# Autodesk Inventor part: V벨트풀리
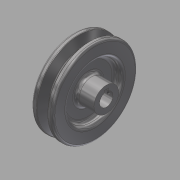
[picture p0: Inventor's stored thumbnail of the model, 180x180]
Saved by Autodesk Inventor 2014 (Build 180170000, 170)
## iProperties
Created: 2015-11
Part Number: V벨트풀리
Material: 강철, 탄소
Document SubType Name: Modeling
Designer: mduedu
Density: 1 g/cm^3
Appearance: 반광택
Author: mduedu
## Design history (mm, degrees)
sketch "스케치1"
  geometry: L1 (-9.5, 0)-(9.5, 0); L2 (0, 0)-(0, 37.7); L3 (-4.825, 37.7)-(-9.5, 37.7); L4 (-9.5, 37.7)-(-9.5, 0); L5 (0, 28.7)-(-2.074, 28.7); L6 (-2.074, 28.7)-(-4.825, 37.7); L7 (4.825, 37.7)-(9.5, 37.7); L8 (9.5, 37.7)-(9.5, 0); L9 (0, 28.7)-(2.074, 28.7); L10 (2.074, 28.7)-(4.825, 37.7); L11 (-9.5, 35)-(9.5, 35); 3 further points
  constraints: 22 end point, 7 point on line, 4 perpendicular, 3 symmetric about line, 1 coincident, 1 horizontal, 1 horizontal alignment, 1 midpoint, 1 vertical
  dimensions: "d0" = 19 distance of L1.start L1.end; "d2" = 75.4 diameter of L2.end L1 (derived); "d3" = 34 deg angle of L10 L6; "d4" = 6.3 distance between parallel lines of L11 L9; "d5" = 2.7 distance between parallel lines of L7 L11; "d6" = 8 distance of point (4, 35) point (-4, 35); "d7" = 70 diameter of L11 L1
revolve "회전1" sketch "스케치1" stored, may be unused: angle "d8" = 90 deg
sketch "스케치2"
  geometry: C1 r 24 at (0, 0); C2 r 11 at (0, 0); 1 further point
  constraints: 2 centre point, 2 coincident
  dimensions: "d9" = 48 diameter of C1; "d10" = 22 diameter of C2
extrude "돌출1" cut sketch "스케치2" distance "d11" = 6; taper "d12" = 0 deg
extrude "돌출3" join sketch "스케치2" distance "d37" = 10; taper "d38" = 0 deg
fillet "모깎기1" dims "d13" = 3
fillet "모깎기2" dims "d14" = 3
fillet "모깎기3" dims "d15" = 1, "d16" = 0.5, "d17" = 2
hole "구멍1" diameter "d20" = 12; stored, may be unused: countersink angle "d24" = 90 deg, drill point angle "d26" = 118 deg; dims "d21" = 6, "d22" = 4, "d23" = 2, "d25" = 8, "d39" = 10, "d40" = 10
sketch "스케치3"
  geometry: L1 (-2, 0)-(2, 0); L2 (2, 0)-(2, 7.8); L3 (2, 7.8)-(-2, 7.8); L4 (-2, 7.8)-(-2, 0); 2 further points
  constraints: 8 end point, 2 parallel, 1 coincident, 1 horizontal, 1 midpoint, 1 perpendicular
  dimensions: "d27" = 4 distance of L2.end L3.end; "d29" = 7.8 distance of L3.end L1.start
extrude "돌출2" cut sketch "스케치3" stored distance "d30" = 6; taper "d31" = 0 deg
chamfer "모따기1" distance "d32" = 0.5; stored, may be unused: second distance "d33" = 2, angle "d34" = 45 deg
node "작업 평면1"
sketch "스케치4"
  geometry: L1 (-19, 11)-(-19, -11) reference; 2 further points
  constraints: 1 horizontal alignment
  dimensions: "d41" = 25 distance from line of point (6, 0) L1
hole "구멍2" sketch "스케치4" at (6, 0) diameter "d42" = 2.459; stored, may be unused: countersink angle "d46" = 90 deg, drill point angle "d48" = 118 deg; dims "d43" = 6, "d44" = 4, "d45" = 2, "d47" = 8
node "솔리드1"
mirror "대칭1"
